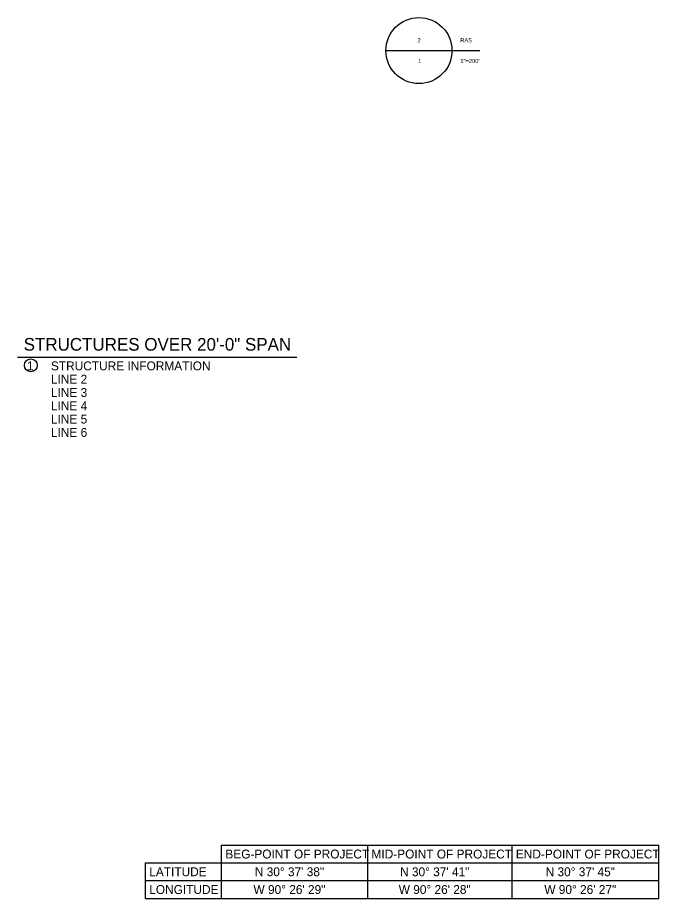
# Model space of a CAD drawing. Extents: x -0.54 to 1.64, y 0 to 0.92.
# Drawn here: x -0.538 to -0.032, y 0.042 to 0.737 of the extents above; entities that cross this region are included whole.
import ezdxf

# ---------------------------------------------------------------- set-up
doc = ezdxf.new("R2010")
doc.units = 0
for name, color, linetype in [('Default', 7, 'Continuous'), ('SHET_Annotations', 7, 'Continuous'), ('SHET_Border-Text', 7, 'Continuous')]:
    doc.layers.add(name, color=color, linetype=linetype)

msp = doc.modelspace()

# ---------------------------------------------------------------- linework, layer by layer
at = {"layer": 'Default'}
for p, q in [((-0.24802617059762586, 0.71065555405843), (-0.19594294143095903, 0.71065555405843)), ((-0.22175817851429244, 0.71065555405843), (-0.17393253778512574, 0.71065555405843))]:
    msp.add_line(p, q, dxfattribs=at)
msp.add_circle((-0.22198455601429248, 0.71065555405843), 0.026041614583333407, dxfattribs=at)
at = {"layer": 'SHET_Annotations'}
msp.add_circle((-0.5279848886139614, 0.46226564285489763), 0.005090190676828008, dxfattribs=at)
at = {"layer": 'SHET_Border-Text'}
for p, q in [((-0.5383979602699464, 0.46887835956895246), (-0.31839796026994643, 0.46887835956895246)), ((-0.37762185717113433, 0.041666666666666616), (-0.37762185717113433, 0.08366666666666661)), ((-0.37762185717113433, 0.08366666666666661), (-0.24762185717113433, 0.08366666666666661)), ((-0.26239720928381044, 0.041666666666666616), (-0.26239720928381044, 0.08366666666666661)), ((-0.24762185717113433, 0.08366666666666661), (-0.11762185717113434, 0.08366666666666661)), ((-0.1486021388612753, 0.041666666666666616), (-0.1486021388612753, 0.08366666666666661)), ((-0.11762185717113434, 0.08366666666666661), (-0.032879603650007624, 0.08366666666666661)), ((-0.032879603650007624, 0.041666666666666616), (-0.032879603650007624, 0.08366666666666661)), ((-0.43762185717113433, 0.041666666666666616), (-0.43762185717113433, 0.06966666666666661)), ((-0.43762185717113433, 0.06966666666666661), (-0.37762185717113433, 0.06966666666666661)), ((-0.37762185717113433, 0.06966666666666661), (-0.24762185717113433, 0.06966666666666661)), ((-0.24762185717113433, 0.06966666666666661), (-0.11762185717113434, 0.06966666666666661)), ((-0.11762185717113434, 0.06966666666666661), (-0.032879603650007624, 0.06966666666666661)), ((-0.43762185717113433, 0.055666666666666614), (-0.37762185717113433, 0.055666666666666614)), ((-0.37762185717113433, 0.055666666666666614), (-0.24762185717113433, 0.055666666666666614)), ((-0.24762185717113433, 0.055666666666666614), (-0.11762185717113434, 0.055666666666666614)), ((-0.11762185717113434, 0.055666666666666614), (-0.032879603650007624, 0.055666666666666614)), ((-0.43762185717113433, 0.041666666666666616), (-0.37762185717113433, 0.041666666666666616)), ((-0.37762185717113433, 0.041666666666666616), (-0.24762185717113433, 0.041666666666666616)), ((-0.24762185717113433, 0.041666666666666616), (-0.11762185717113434, 0.041666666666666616)), ((-0.11762185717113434, 0.041666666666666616), (-0.032879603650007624, 0.041666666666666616))]:
    msp.add_line(p, q, dxfattribs=at)

# ---------------------------------------------------------------- texts
at = {"layer": 'Default'}
for s, p in [('2', (-0.22313734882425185, 0.7172172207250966)), ('RAS', (-0.18943253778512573, 0.7172172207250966)), ('1', (-0.2226108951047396, 0.70081305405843)), ('1"=200\'', (-0.18943253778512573, 0.70081305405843))]:
    msp.add_text(s, height=0.0032808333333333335, dxfattribs=at).set_placement(p)
at = {"layer": 'SHET_Annotations'}
for s, p in [('1', (-0.531102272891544, 0.45837835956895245)), ('STRUCTURE INFORMATION', (-0.5121431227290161, 0.45837835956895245)), ('LINE 2', (-0.5121431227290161, 0.44787835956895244)), ('LINE 3', (-0.5121431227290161, 0.4373783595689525)), ('LINE 4', (-0.5121431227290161, 0.4268783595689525)), ('LINE 5', (-0.5121431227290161, 0.41637835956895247)), ('LINE 6', (-0.5121431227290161, 0.40587835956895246)), ('N 30° 37\' 38"', (-0.35138962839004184, 0.05916666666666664)), ('N 30° 37\' 41"', (-0.23687976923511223, 0.05916666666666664)), ('N 30° 37\' 45"', (-0.1221209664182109, 0.05916666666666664)), ('W 90° 26\' 29"', (-0.35244628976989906, 0.04516666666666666)), ('W 90° 26\' 28"', (-0.23793643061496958, 0.04516666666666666)), ('W 90° 26\' 27"', (-0.12317762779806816, 0.04516666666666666))]:
    msp.add_text(s, height=0.006999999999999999, dxfattribs=at).set_placement(p)
at = {"layer": 'SHET_Border-Text'}
for s, height, p in [('STRUCTURES OVER 20\'-0" SPAN', 0.01, (-0.5336303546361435, 0.4738783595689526)), ('BEG-POINT OF PROJECT', 0.006999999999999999, (-0.37462185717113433, 0.07316666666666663)), ('MID-POINT OF PROJECT', 0.006999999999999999, (-0.25939720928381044, 0.07316666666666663)), ('END-POINT OF PROJECT', 0.006999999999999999, (-0.1456021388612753, 0.07316666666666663)), ('LATITUDE', 0.006999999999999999, (-0.4346218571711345, 0.05916666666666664)), ('LONGITUDE', 0.006999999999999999, (-0.4346218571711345, 0.04516666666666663))]:
    msp.add_text(s, height=height, dxfattribs=at).set_placement(p)

doc.saveas('drawing.dxf')
